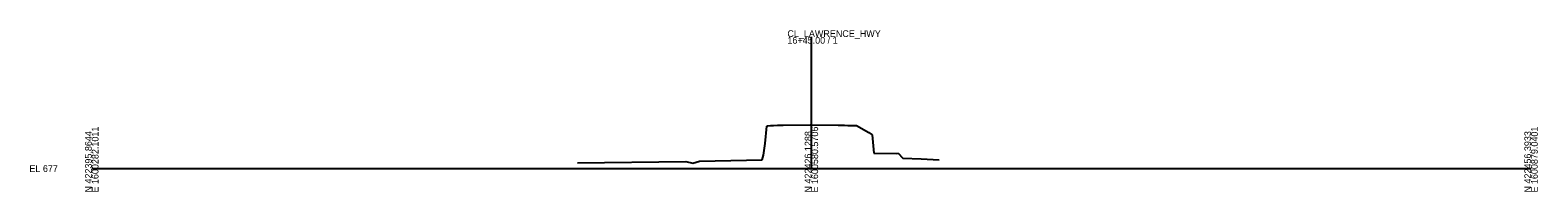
# Model space of a CAD drawing. Extents: x -635 to 1600611, y -10 to 422386.
# Drawn here: x -26 to 603, y 36990 to 37058 of the extents above; entities that cross this region are included whole.
import ezdxf

# ---------------------------------------------------------------- set-up
doc = ezdxf.new("R2010")
doc.units = 0
doc.layers.add('DESIGN - SHEET - Light Grid', color=7, linetype='Continuous')
doc.layers.add('SURVEY - GROUND - Top of Ground', color=7, linetype='Continuous')

msp = doc.modelspace()

# ---------------------------------------------------------------- linework, layer by layer
at = {"layer": 'DESIGN - SHEET - Light Grid'}
for p, q in [((300, 37000), (300, 37054.83)), ((0, 37000), (300, 37000)), ((300, 37000), (600, 37000))]:
    msp.add_line(p, q, dxfattribs=at)
at = {"layer": 'SURVEY - GROUND - Top of Ground'}
for p, q in [((280.74, 37010.42), (281.45, 37017.69)), ((281.45, 37017.69), (281.63, 37017.77)), ((281.63, 37017.77), (282.89, 37017.91)), ((282.89, 37017.91), (284.2, 37017.92)), ((284.2, 37017.92), (285.88, 37018.03)), ((285.88, 37018.03), (288.25, 37018.05)), ((288.25, 37018.05), (299.42, 37018.28)), ((299.42, 37018.28), (300.11, 37018.27)), ((300.11, 37018.27), (311.13, 37018.03)), ((311.13, 37018.03), (313.74, 37018.08)), ((313.74, 37018.08), (315.14, 37017.91)), ((315.14, 37017.91), (318.84, 37017.97)), ((318.84, 37017.97), (323.9, 37015.04)), ((323.9, 37015.04), (325.36, 37014.09)), ((279.97, 37005.6), (280.74, 37010.42)), ((325.36, 37014.09), (325.99, 37006.44)), ((202.42, 37002.36), (247.71, 37002.92)), ((247.71, 37002.92), (250.54, 37002.26)), ((250.54, 37002.26), (253.28, 37003.12)), ((253.28, 37003.12), (279.47, 37003.7)), ((279.47, 37003.7), (279.97, 37005.6)), ((325.99, 37006.44), (335.35, 37006.3)), ((335.35, 37006.3), (336.13, 37006.47)), ((336.13, 37006.47), (338.08, 37004.29)), ((338.08, 37004.29), (345.77, 37004.1)), ((345.77, 37004.1), (353.2, 37003.64))]:
    msp.add_line(p, q, dxfattribs=at)

# ---------------------------------------------------------------- texts
at = {"layer": 'DESIGN - SHEET - Light Grid'}
for s, p in [('CL_LAWRENCE_HWY', (290, 37054.83)), ('16+45.00 / 1', (290, 37052.03)), ('EL 677', (-26, 36998.6))]:
    msp.add_text(s, height=2.8, dxfattribs=at).set_placement(p)
for s, p in [('N 422395.8644', (0, 36990)), ('E 1600282.1011', (2.8, 36990)), ('N 422426.1288', (300, 36990)), ('E 1600580.5706', (302.8, 36990)), ('N 422456.3933', (600, 36990)), ('E 1600879.0401', (602.8, 36990))]:
    msp.add_text(s, height=2.8, rotation=90, dxfattribs=at).set_placement(p)

doc.saveas('drawing.dxf')
